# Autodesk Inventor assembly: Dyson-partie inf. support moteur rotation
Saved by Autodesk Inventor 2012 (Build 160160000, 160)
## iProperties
Created: 2012-11
Part Number: Dyson-partie inf. support moteur rotation
Document SubType Name: Assembly
Designer: Administrateur
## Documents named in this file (4)
- F:\Dyson\SI\2_Présentation éleve\SW_AM01 complet\Composants importés\Dyson Air Multiplier-Assemblage final\Dyson-partie inf. support moteur rotation.iam
- F:\Dyson\SI\2_Présentation éleve\SW_AM01 complet\Composants importés\Dyson Air Multiplier-Assemblage final\Dyson-Partie inf. support moteur noir.ipt
- F:\Dyson\SI\2_Présentation éleve\SW_AM01 complet\Composants importés\Dyson Air Multiplier-Assemblage final\Dyson-Partie inf.moteur rotation.ipt
- F:\Dyson\SI\2_Présentation éleve\SW_AM01 complet\Composants importés\Dyson Air Multiplier-Assemblage final\Dyson-Partie inf.pivot blanc.ipt
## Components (3 placed, 3 different names)
1. Dyson-Partie inf. support moteur noir:1
2. Dyson-Partie inf.moteur rotation:1
3. Dyson-Partie inf.pivot blanc:1
